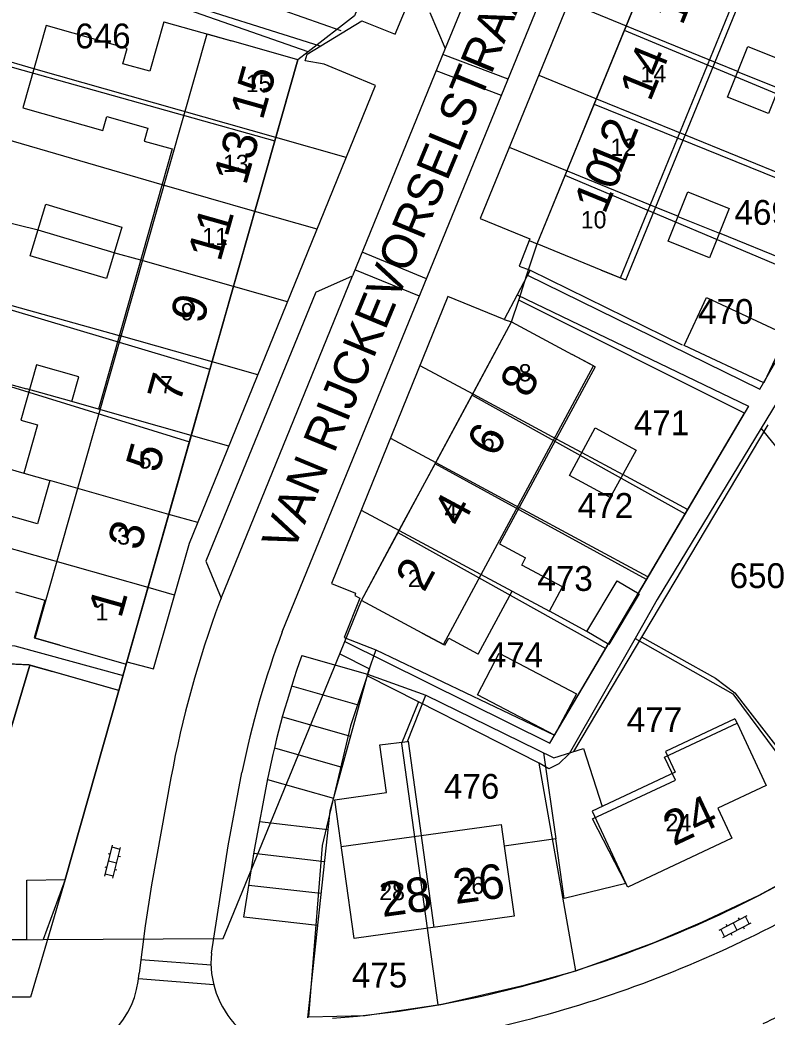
# Model space of a CAD drawing. Extents: x 148816 to 151297, y 399515 to 402500.
# Drawn here: x 150084.3 to 150138.5, y 400394.8 to 400467.1 of the extents above; entities that cross this region are included whole.
import ezdxf

# ---------------------------------------------------------------- set-up
doc = ezdxf.new("R2010")
doc.units = 0
for name, color, linetype in [('B01 Hoofdgebouw  [D] Norm', 7, 'Continuous'), ('B01 Hoofdgebouw  [T] Norm', 7, 'Continuous'), ('B01 hoofgebouw', 7, 'Continuous'), ('B02 Bijgebouw  [D] Norm', 7, 'Continuous'), ('B07 Tussenmuur  [D] Norm', 7, 'Continuous'), ('G01 perceelsgrens', 7, 'Continuous'), ('S02 Open verharding  Norm', 7, 'Continuous'), ('T04 Haag heg  [D] Gem', 7, 'Continuous'), ('V00 Kant verharding algemeen  [T] Norm', 7, 'Continuous'), ('V00 Kant verharding algemeen secundair  [T] Gem', 7, 'Continuous'), ('Z01 perceelnummer', 7, 'Continuous'), ('Z02 huisnummer', 7, 'Continuous'), ('Z02 Huisnummer  [Tekst] Norm', 7, 'Continuous'), ('Z06 straatnaam', 7, 'Continuous')]:
    doc.layers.add(name, color=color, linetype=linetype)

msp = doc.modelspace()

# ---------------------------------------------------------------- linework, layer by layer
at = {"layer": 'B01 Hoofdgebouw  [D] Norm'}
for p, q in [((150128.228, 400448.251), (150143.245, 400484.984)), ((150094.755, 400466.984), (150093.739, 400463.395)), ((150094.755, 400466.984), (150099.67, 400465.6)), ((150086.252, 400466.715), (150084.557, 400460.736)), ((150092.107, 400465.055), (150086.252, 400466.715)), ((150091.793, 400463.946), (150092.107, 400465.055)), ((150093.739, 400463.395), (150091.793, 400463.946)), ((150084.557, 400460.736), (150090.342, 400459.096)), ((150090.342, 400459.096), (150090.634, 400460.126)), ((150090.634, 400460.126), (150093.608, 400459.282)), ((150093.608, 400459.282), (150093.341, 400458.341)), ((150093.341, 400458.341), (150095.374, 400457.764)), ((150095.374, 400457.764), (150090.024, 400438.905)), ((150091.16, 400450.235), (150085.652, 400451.887)), ((150128.228, 400448.251), (150126.43, 400448.99)), ((150125.994, 400441.985), (150124.35, 400442.87)), ((150085.549, 400442.125), (150084.41, 400438.114)), ((150088.615, 400441.254), (150085.549, 400442.125)), ((150125.994, 400441.985), (150119.086, 400429.154)), ((150088.103, 400439.45), (150088.615, 400441.254)), ((150088.103, 400439.45), (150084.807, 400440.375)), ((150090.024, 400438.905), (150088.103, 400439.45)), ((150084.41, 400438.114), (150085.621, 400437.77)), ((150085.621, 400437.77), (150084.624, 400434.265)), ((150084.624, 400434.265), (150086.504, 400433.73)), ((150086.504, 400433.73), (150085.61, 400430.589)), ((150085.61, 400430.589), (150078.403, 400432.64)), ((150119.086, 400429.154), (150120.967, 400428.141)), ((150120.682, 400427.611), (150120.967, 400428.141)), ((150123.64, 400426.021), (150120.682, 400427.611)), ((150122.692, 400424.258), (150123.64, 400426.021)), ((150084.019, 400425.664), (150086.151, 400425.058)), ((150117.542, 400421.144), (150119.996, 400425.708)), ((150119.996, 400425.708), (150122.692, 400424.258)), ((150086.151, 400425.058), (150085.374, 400422.323)), ((150085.374, 400422.323), (150087.229, 400421.796)), ((150115.124, 400421.795), (150113.48, 400422.68)), ((150115.124, 400421.795), (150115.396, 400422.3)), ((150115.396, 400422.3), (150117.505, 400421.164)), ((150136.131, 400416.463), (150131.091, 400414.097)), ((150136.131, 400416.463), (150136.28, 400416.16)), ((150118.22, 400415.98), (150123.015, 400413.641)), ((150114.34, 400401.35), (150112.476, 400414.839)), ((150122.262, 400414.008), (150123.15, 400407.76)), ((150131.091, 400414.097), (150131.8, 400412.587)), ((150131.8, 400412.587), (150125.79, 400409.766)), ((150125.79, 400409.766), (150128.23, 400404.54))]:
    msp.add_line(p, q, dxfattribs=at)
for points in [[(150082.646, 400412.311), (150085.059, 400420.354), (150086.7, 400419.89)], [(150123.015, 400413.641), (150125.167, 400414.314), (150126.515, 400410.106)]]:
    msp.add_lwpolyline(points, dxfattribs=at)
at = {"layer": 'B01 Hoofdgebouw  [T] Norm'}
for p, q in [((150121.8, 400450.88), (150141.88, 400500)), ((150104.48, 400464.23), (150099.67, 400465.6)), ((150092.04, 400420.43), (150104.48, 400464.23)), ((150126.43, 400448.99), (150121.8, 400450.88)), ((150109.08, 400425.05), (150119.95, 400445.24)), ((150119.95, 400445.24), (150124.35, 400442.87)), ((150113.48, 400422.68), (150109.08, 400425.05)), ((150087.23, 400421.8), (150092.04, 400420.43)), ((150091.51, 400418.52), (150086.7, 400419.89)), ((150087.61, 400404.81), (150091.51, 400418.52)), ((150112.41, 400414.83), (150113.73, 400418.17)), ((150113.73, 400418.17), (150118.22, 400415.98)), ((150136.28, 400416.16), (150138.4, 400411.63)), ((150110.4, 400414.57), (150112.41, 400414.83)), ((150110.89, 400411.12), (150110.4, 400414.57)), ((150138.4, 400411.63), (150134.88, 400409.98)), ((150107.14, 400410.59), (150110.89, 400411.12)), ((150108.55, 400400.55), (150107.14, 400410.59)), ((150134.88, 400409.98), (150135.91, 400407.81)), ((150123.15, 400407.76), (150119.42, 400407.23)), ((150123.77, 400403.45), (150123.15, 400407.76)), ((150135.91, 400407.81), (150128.37, 400404.27)), ((150119.42, 400407.23), (150120.13, 400402.15)), ((150084.84, 400404.77), (150087.61, 400404.81)), ((150084.85, 400400.47), (150084.84, 400404.77)), ((150128.23, 400404.54), (150123.77, 400403.45)), ((150128.37, 400404.27), (150128.23, 400404.54)), ((150120.13, 400402.15), (150108.55, 400400.55)), ((150039.34, 400400.24), (150084.85, 400400.47))]:
    msp.add_line(p, q, dxfattribs=at)
at = {"layer": 'B01 hoofgebouw'}
for points in [[(150126.43, 400448.99), (150121.8, 400450.88), (150141.881, 400500)], [(150126.43, 400448.99), (150127.838, 400448.415), (150148.927, 400500)], [(150087.23, 400421.8), (150085.455, 400422.306), (150097.895, 400466.106), (150099.67, 400465.6)], [(150087.23, 400421.8), (150092.04, 400420.43), (150092.085, 400420.588), (150104.48, 400464.23), (150099.67, 400465.6)], [(150113.48, 400422.68), (150109.08, 400425.05), (150119.95, 400445.24), (150124.35, 400442.87)], [(150113.48, 400422.68), (150115.022, 400421.849), (150125.892, 400442.039), (150124.35, 400442.87)], [(150086.7, 400419.89), (150085.059, 400420.354), (150082.646, 400412.311)], [(150047.13, 400412.59), (150043.13, 400412.53), (150043.1, 400409.36), (150042.08, 400409.33), (150042.15, 400407.22), (150039.32, 400407.19), (150039.34, 400400.24), (150084.85, 400400.47), (150084.84, 400404.77), (150087.61, 400404.81), (150091.51, 400418.52), (150086.7, 400419.89)], [(150136.28, 400416.16), (150138.4, 400411.63), (150134.88, 400409.98), (150135.91, 400407.81), (150128.37, 400404.27), (150128.23, 400404.54), (150123.77, 400403.45), (150123.15, 400407.76), (150119.42, 400407.23), (150120.13, 400402.15), (150108.55, 400400.55), (150107.14, 400410.59), (150110.89, 400411.12), (150110.4, 400414.57), (150112.41, 400414.83), (150113.73, 400418.17), (150118.22, 400415.98)], [(150128.23, 400404.54), (150125.809, 400409.209), (150131.814, 400412.028), (150131.031, 400413.696), (150136.28, 400416.16)], [(150107.616, 400407.2), (150119.2, 400408.801), (150119.42, 400407.23)]]:
    msp.add_lwpolyline(points, dxfattribs=at)
at = {"layer": 'B02 Bijgebouw  [D] Norm'}
for p, q in [((150136.332, 400463.358), (150139.3, 400462.168)), ((150132.001, 400452.879), (150134.999, 400451.672)), ((150125.044, 400435.765), (150128.01, 400434.168))]:
    msp.add_line(p, q, dxfattribs=at)
for points in [[(150135.598, 400461.528), (150137.067, 400465.19), (150140.035, 400464), (150138.566, 400460.338)], [(150131.281, 400451.091), (150132.722, 400454.669), (150135.72, 400453.461), (150134.279, 400449.883)], [(150086.211, 400453.753), (150091.72, 400452.102), (150090.601, 400448.368), (150085.092, 400450.019)], [(150138.221, 400440.814), (150132.441, 400443.53), (150134.073, 400447.002), (150139.853, 400444.286)], [(150124.137, 400434.099), (150126.015, 400437.547), (150128.964, 400435.941), (150127.086, 400432.493)], [(150129.182, 400425.512), (150126.987, 400421.849), (150125.408, 400422.795), (150127.603, 400426.458)], [(150119.054, 400421.211), (150124.646, 400418.275), (150123.071, 400415.276), (150117.479, 400418.212)]]:
    msp.add_lwpolyline(points, close=True, dxfattribs=at)
at = {"layer": 'B07 Tussenmuur  [D] Norm'}
for p, q in [((150128.259, 400466.681), (150134.688, 400464.053)), ((150128.259, 400466.681), (150134.688, 400464.053)), ((150102.881, 400458.599), (150085.352, 400463.577)), ((150102.881, 400458.599), (150085.352, 400463.577)), ((150126.103, 400461.406), (150132.531, 400458.778)), ((150126.103, 400461.406), (150132.531, 400458.778)), ((150123.967, 400456.182), (150130.396, 400453.554)), ((150123.967, 400456.182), (150130.396, 400453.554)), ((150101.36, 400453.243), (150094.634, 400455.154)), ((150101.36, 400453.243), (150094.634, 400455.154)), ((150099.81, 400447.786), (150093.085, 400449.696)), ((150099.81, 400447.786), (150093.085, 400449.696)), ((150098.261, 400442.335), (150091.539, 400444.244)), ((150098.261, 400442.335), (150091.539, 400444.244)), ((150117.14, 400440.021), (150123.184, 400436.766)), ((150117.14, 400440.021), (150123.184, 400436.766)), ((150096.745, 400436.996), (150090.024, 400438.905)), ((150096.745, 400436.996), (150090.024, 400438.905)), ((150114.456, 400435.036), (150120.501, 400431.782)), ((150114.456, 400435.036), (150120.501, 400431.782)), ((150095.122, 400431.282), (150086.504, 400433.73)), ((150095.122, 400431.282), (150086.504, 400433.73)), ((150093.616, 400425.978), (150077.786, 400430.474)), ((150093.616, 400425.978), (150077.786, 400430.474)), ((150111.808, 400430.116), (150119.996, 400425.708)), ((150111.808, 400430.116), (150119.996, 400425.708))]:
    msp.add_line(p, q, dxfattribs=at)
at = {"layer": 'G01 perceelsgrens'}
for points in [[(150119.122, 400493.173), (150108.58, 400467.42), (150105.224, 400464.809)], [(150105.224, 400464.809), (150082.637, 400472.707), (150080.655, 400464.655), (150083.178, 400463.851), (150102.812, 400458.358)], [(150128.122, 400466.343), (150130.285, 400471.634)], [(150125.943, 400461.013), (150128.122, 400466.343)], [(150148.115, 400458.019), (150128.122, 400466.343)], [(150105.224, 400464.809), (150104.48, 400464.23), (150102.812, 400458.358)], [(150123.826, 400455.835), (150125.943, 400461.013)], [(150125.943, 400461.013), (150145.314, 400453.155)], [(150102.812, 400458.358), (150098.104, 400441.781)], [(150121.063, 400448.634), (150121.8, 400450.88), (150123.826, 400455.835)], [(150142.348, 400448.004), (150123.826, 400455.835)], [(150098.104, 400441.781), (150076.019, 400448.386), (150074.648, 400443.333), (150096.618, 400436.548)], [(150120.466, 400446.812), (150121.063, 400448.634)], [(150121.063, 400448.634), (150137.94, 400440.348), (150142.348, 400448.004)], [(150117.089, 400439.926), (150119.95, 400445.24), (150120.466, 400446.812)], [(150132.523, 400431.322), (150136.814, 400438.61), (150120.466, 400446.812)], [(150142.601, 400445.051), (150138.036, 400437.523)], [(150098.104, 400441.781), (150096.618, 400436.548)], [(150114.41, 400434.95), (150117.089, 400439.926)], [(150117.089, 400439.926), (150132.523, 400431.322)], [(150138.036, 400437.523), (150130.503, 400425.103), (150128.898, 400422.287)], [(150155.97, 400416.13), (150149.978, 400422.828), (150146.093, 400427.641), (150138.036, 400437.523)], [(150096.618, 400436.548), (150092.04, 400420.43), (150091.51, 400418.52)], [(150111.723, 400429.96), (150114.41, 400434.95)], [(150129.722, 400426.565), (150114.41, 400434.95)], [(150129.722, 400426.565), (150132.523, 400431.322)], [(150107.861, 400422.065), (150109.08, 400425.05), (150111.723, 400429.96)], [(150111.723, 400429.96), (150126.782, 400421.572)], [(150126.782, 400421.572), (150129.722, 400426.565)], [(150128.898, 400422.287), (150124.133, 400413.929), (150123.376, 400413.211), (150122.651, 400412.837), (150121.937, 400413.24)], [(150128.898, 400422.287), (150135.97, 400418.267), (150144.143, 400407.277)], [(150107.499, 400421.178), (150107.861, 400422.065)], [(150107.861, 400422.065), (150122.731, 400414.691), (150126.782, 400421.572)], [(150086.033, 400400.476), (150099.07, 400400.542), (150107.499, 400421.178)], [(150107.499, 400421.178), (150109.668, 400420.097), (150109.496, 400419.578)], [(150091.51, 400418.52), (150084.994, 400420.376), (150078.709, 400420.674), (150079.14, 400400.441)], [(150109.496, 400419.578), (150108.295, 400415.954), (150106.221, 400407.271), (150105.69, 400400.62), (150105.25, 400394.87), (150109.35, 400394.95), (150114.619, 400395.746)], [(150113.217, 400417.683), (150109.496, 400419.578)], [(150091.51, 400418.52), (150087.61, 400404.81), (150086.033, 400400.476)], [(150113.217, 400417.683), (150111.966, 400414.665), (150114.619, 400395.746)], [(150121.937, 400413.24), (150113.217, 400417.683)], [(150124.61, 400398.21), (150121.937, 400413.24)], [(150124.61, 400398.21), (150127.58, 400399.26), (150130.27, 400400.26), (150133.79, 400401.75), (150137.83, 400403.66), (150141.27, 400405.51), (150144.143, 400407.277)], [(150079.14, 400400.441), (150086.033, 400400.476)], [(150114.619, 400395.746), (150115.11, 400395.82), (150120.87, 400397.16), (150124.61, 400398.21)]]:
    msp.add_lwpolyline(points, dxfattribs=at)
at = {"layer": 'S02 Open verharding  Norm'}
for p, q in [((150090.48, 400405.067), (150091.046, 400407.296)), ((150091.591, 400407.004), (150091.009, 400407.151)), ((150091.062, 400404.92), (150091.628, 400407.149)), ((150090.741, 400406.703), (150090.886, 400406.666)), ((150091.468, 400406.519), (150091.613, 400406.482)), ((150090.495, 400405.734), (150090.64, 400405.697)), ((150090.763, 400406.182), (150091.345, 400406.034)), ((150091.099, 400405.065), (150090.517, 400405.212)), ((150091.222, 400405.55), (150091.367, 400405.513)), ((150134.975, 400401.154), (150137.02, 400402.207)), ((150136.374, 400402.043), (150136.442, 400401.91)), ((150137.161, 400401.605), (150136.887, 400402.138)), ((150135.383, 400400.69), (150135.109, 400401.223)), ((150135.25, 400400.621), (150137.295, 400401.674)), ((150135.484, 400401.585), (150135.553, 400401.452)), ((150135.998, 400401.681), (150136.272, 400401.147)), ((150136.717, 400401.376), (150136.786, 400401.243)), ((150135.828, 400400.918), (150135.896, 400400.785))]:
    msp.add_line(p, q, dxfattribs=at)
at = {"layer": 'T04 Haag heg  [D] Gem'}
for p, q in [((150124.075, 400468.392), (150128.259, 400466.681)), ((150085.352, 400463.577), (150081.05, 400464.828)), ((150134.688, 400464.053), (150136.352, 400463.373)), ((150121.918, 400463.117), (150126.103, 400461.406)), ((150094.634, 400455.154), (150079.361, 400459.609)), ((150107.976, 400457.152), (150102.881, 400458.599)), ((150132.531, 400458.778), (150145.457, 400453.493)), ((150119.781, 400457.893), (150123.967, 400456.182)), ((150130.396, 400453.554), (150132.018, 400452.892)), ((150085.652, 400451.887), (150081.284, 400452.943)), ((150105.869, 400451.962), (150101.36, 400453.243)), ((150121.216, 400451.119), (150121.8, 400450.88)), ((150142.518, 400448.598), (150134.999, 400451.672)), ((150093.085, 400449.696), (150091.135, 400450.247)), ((150076.279, 400448.503), (150091.539, 400444.244)), ((150103.723, 400446.674), (150099.81, 400447.786)), ((150119.42, 400445.41), (150119.95, 400445.24)), ((150074.778, 400443.173), (150084.807, 400440.375)), ((150101.579, 400441.392), (150098.261, 400442.335)), ((150113.312, 400442.082), (150117.14, 400440.021)), ((150073.302, 400437.513), (150084.624, 400434.265)), ((150099.479, 400436.219), (150096.745, 400436.996)), ((150111.171, 400436.805), (150114.456, 400435.036)), ((150123.184, 400436.766), (150125.044, 400435.765)), ((150132.7, 400431.643), (150128.01, 400434.168)), ((150109.058, 400431.597), (150111.808, 400430.116)), ((150129.828, 400426.761), (150120.501, 400431.782)), ((150097.232, 400430.683), (150095.122, 400431.282)), ((150095.547, 400425.43), (150093.616, 400425.978)), ((150125.408, 400422.796), (150122.692, 400424.258))]:
    msp.add_line(p, q, dxfattribs=at)
msp.add_lwpolyline([(150129.37, 400422.402), (150134.725, 400419.42), (150136.112, 400418.347), (150137.042, 400417.167), (150144.559, 400407.505)], dxfattribs=at)
at = {"layer": 'V00 Kant verharding algemeen  [T] Norm'}
for p, q in [((150103.34, 400422.76), (150134.885, 400500)), ((150111.53, 400466.09), (150125.425, 400500)), ((150137, 400500), (150117.67, 400452.73)), ((150107.599, 400466.332), (150084.25, 400474.569)), ((150106.091, 400465.205), (150083.493, 400472.381)), ((150105.15, 400464.63), (150109.11, 400467.05)), ((150109.11, 400467.05), (150111.53, 400466.09)), ((150114.025, 400467.657), (150115.139, 400465.034)), ((150115.139, 400465.034), (150108.433, 400448.58)), ((150105, 400464.16), (150105.15, 400464.63)), ((150106.37, 400463.9), (150105, 400464.16)), ((150110.09, 400462.36), (150106.37, 400463.9)), ((150096.63, 400429.2), (150110.09, 400462.36)), ((150117.67, 400452.73), (150121.27, 400451.25)), ((150121.27, 400451.25), (150120.51, 400449.27)), ((150121.3, 400448.97), (150119.42, 400445.41)), ((150120.51, 400449.27), (150121.3, 400448.97)), ((150105.771, 400447.38), (150108.433, 400448.58)), ((150105.771, 400447.38), (150097.812, 400427.89)), ((150115.34, 400447.08), (150106.9, 400426.28)), ((150119.42, 400445.41), (150115.34, 400447.08)), ((150094.01, 400420.08), (150096.63, 400429.2)), ((150097.812, 400427.89), (150098.904, 400425.199)), ((150106.9, 400426.28), (150108.65, 400425.56)), ((150098.904, 400425.199), (150098.79, 400424.92)), ((150108.95, 400425.22), (150107.83, 400422.35)), ((150108.65, 400425.56), (150108.59, 400425.41)), ((150108.59, 400425.41), (150108.95, 400425.22)), ((150107.83, 400422.35), (150110.11, 400421.47)), ((150110.11, 400421.47), (150109.57, 400419.88)), ((150123.071, 400415.276), (150126.951, 400421.871)), ((150104.76, 400421.055), (150109.519, 400419.694)), ((150091.51, 400418.52), (150092.04, 400420.43)), ((150092.08, 400420.59), (150094.01, 400420.08)), ((150109.57, 400419.88), (150106.79, 400409.77)), ((150095.27, 400412.18), (150093.88, 400404.44)), ((150099.42, 400407.26), (150100.42, 400412.58)), ((150106.79, 400409.77), (150105.16, 400394.8)), ((150098.21, 400399.48), (150099.42, 400407.26)), ((150087.61, 400404.81), (150085.11, 400396.29)), ((150093.88, 400404.44), (150093.42, 400401.46)), ((150105.887, 400401.476), (150100.563, 400402.091)), ((150093.42, 400401.46), (150092.97, 400398.03)), ((150085.11, 400396.29), (150036.1, 400396.27))]:
    msp.add_line(p, q, dxfattribs=at)
for points in [[(150076.813, 400450.432), (150070.376, 400426.853), (150071.821, 400423.069), (150083.959, 400421.743), (150091.809, 400419.598)], [(150121.3, 400448.97), (150132.315, 400443.577)], [(150120.366, 400447.201), (150137.1, 400439.124), (150129.116, 400425.551)], [(150138.508, 400437.77), (150124.434, 400414.101)], [(150085.059, 400420.354), (150059.734, 400421.562), (150056.482, 400421.545)], [(150110.11, 400421.47), (150123.071, 400415.276)], [(150109.519, 400419.694), (150113.73, 400418.17)]]:
    msp.add_lwpolyline(points, dxfattribs=at)
for centre, radius, start, end in [((150173.769, 400397.347), 79.888, 159.80963, 169.29994), ((150163.876, 400399.887), 64.713, 159.30154, 168.68876), ((150098.979, 400479.848), 87.976, 295.34579, 307.20859), ((150099.395, 400478.558), 84.192, 288.42107, 302.49844), ((150099.521, 400477.791), 85.886, 282.77347, 295.6066), ((150104.84, 400398.813), 6.663, 174.25853, 275.42666), ((150101.132, 400471.251), 76.713, 274.36423, 288.91491), ((150086.445, 400398.386), 6.535, 274.34437, 356.87764), ((150103.099, 400472.65), 85.763, 294.14494, 297.34427)]:
    msp.add_arc(centre, radius, start, end, dxfattribs=at)
at = {"layer": 'V00 Kant verharding algemeen secundair  [T] Gem'}
for p, q in [((150129.39, 400500), (150115.139, 400465.034)), ((150119.698, 400462.813), (150114.962, 400464.601)), ((150119.214, 400461.628), (150114.48, 400463.416)), ((150113.797, 400448.364), (150109.127, 400450.282)), ((150113.276, 400447.088), (150108.607, 400449.006)), ((150098.904, 400425.199), (150108.433, 400448.58)), ((150104.014, 400418.844), (150108.901, 400417.446)), ((150103.352, 400416.61), (150108.283, 400415.2)), ((150102.773, 400414.353), (150107.665, 400412.953)), ((150101.32, 400406.964), (150102.308, 400412.224)), ((150102.278, 400412.071), (150107.048, 400410.707)), ((150106.643, 400408.424), (150101.702, 400408.995)), ((150100.563, 400402.091), (150101.32, 400406.964)), ((150106.391, 400406.108), (150101.27, 400406.7)), ((150106.139, 400403.792), (150100.921, 400404.395)), ((150098.18, 400398.602), (150093.097, 400398.997)), ((150098.379, 400397.185), (150092.934, 400397.608))]:
    msp.add_line(p, q, dxfattribs=at)
msp.add_arc((150163.876, 400399.887), 62.792, 160.29841, 168.68876, dxfattribs=at)

# ---------------------------------------------------------------- texts
at = {"layer": 'Z01 perceelnummer'}
for s, p in [('646', (150088.341, 400465.055)), ('469', (150136.095, 400452.266)), ('470', (150133.454, 400445.087)), ('471', (150128.805, 400437.02)), ('472', (150124.742, 400431.027)), ('473', (150121.816, 400425.734)), ('650', (150135.74, 400425.94)), ('474', (150118.22, 400420.202)), ('477', (150128.291, 400415.5)), ('476', (150115.047, 400410.67)), ('475', (150108.379, 400396.99))]:
    msp.add_text(s, height=1.8, dxfattribs=at).set_placement(p)
at = {"layer": 'Z02 huisnummer'}
for s, rotation, p in [('16', 67.79436, (150132.317, 400466.652)), ('14', 67.79436, (150129.993, 400461.129)), ('15', 74.15692, (150101.918, 400459.785)), ('12', 67.79436, (150127.8, 400455.862)), ('13', 74.15692, (150100.711, 400455.066)), ('10', 67.79436, (150126.702, 400452.963)), ('11', 74.15692, (150098.855, 400449.523)), ('9', 74.15692, (150097.597, 400445.002)), ('8', 61.71864, (150121.176, 400439.607)), ('7', 74.15692, (150095.92, 400439.249)), ('6', 61.71864, (150118.793, 400435.323)), ('5', 74.15692, (150094.362, 400434.212)), ('4', 61.71864, (150116.326, 400430.238)), ('3', 74.15692, (150093.045, 400428.582)), ('2', 61.71864, (150113.617, 400425.567)), ('1', 74.15692, (150091.664, 400423.686)), ('24', 25.15537, (150131.688, 400407.209)), ('26', 7.87092, (150115.888, 400403.031)), ('28', 7.87092, (150110.601, 400402.094))]:
    msp.add_text(s, height=2.5, rotation=rotation, dxfattribs=at).set_placement(p)
at = {"layer": 'Z02 Huisnummer  [Tekst] Norm'}
for s, p in [('14', (150129.292, 400462.6)), ('15', (150100.696, 400461.888)), ('12', (150127.109, 400457.261)), ('13', (150099.05, 400456.093)), ('10', (150124.962, 400452.009)), ('11', (150097.546, 400450.796)), ('9', (150095.997, 400445.344)), ('8', (150120.464, 400440.921)), ('7', (150094.496, 400440.057)), ('6', (150117.799, 400435.97)), ('5', (150092.947, 400434.605)), ('4', (150115.084, 400430.928)), ('3', (150091.381, 400429.09)), ('2', (150112.437, 400426.011)), ('1', (150089.82, 400423.592)), ('24', (150131.105, 400408.315)), ('26', (150116.107, 400403.77)), ('28', (150110.365, 400403.325))]:
    msp.add_text(s, height=1.25, dxfattribs=at).set_placement(p)
at = {"layer": 'Z06 straatnaam'}
msp.add_text('VAN RIJCKEVORSELSTRAAT', height=2.5, rotation=67.48589, dxfattribs=at).set_placement((150104.108, 400428.433))

doc.saveas('drawing.dxf')
